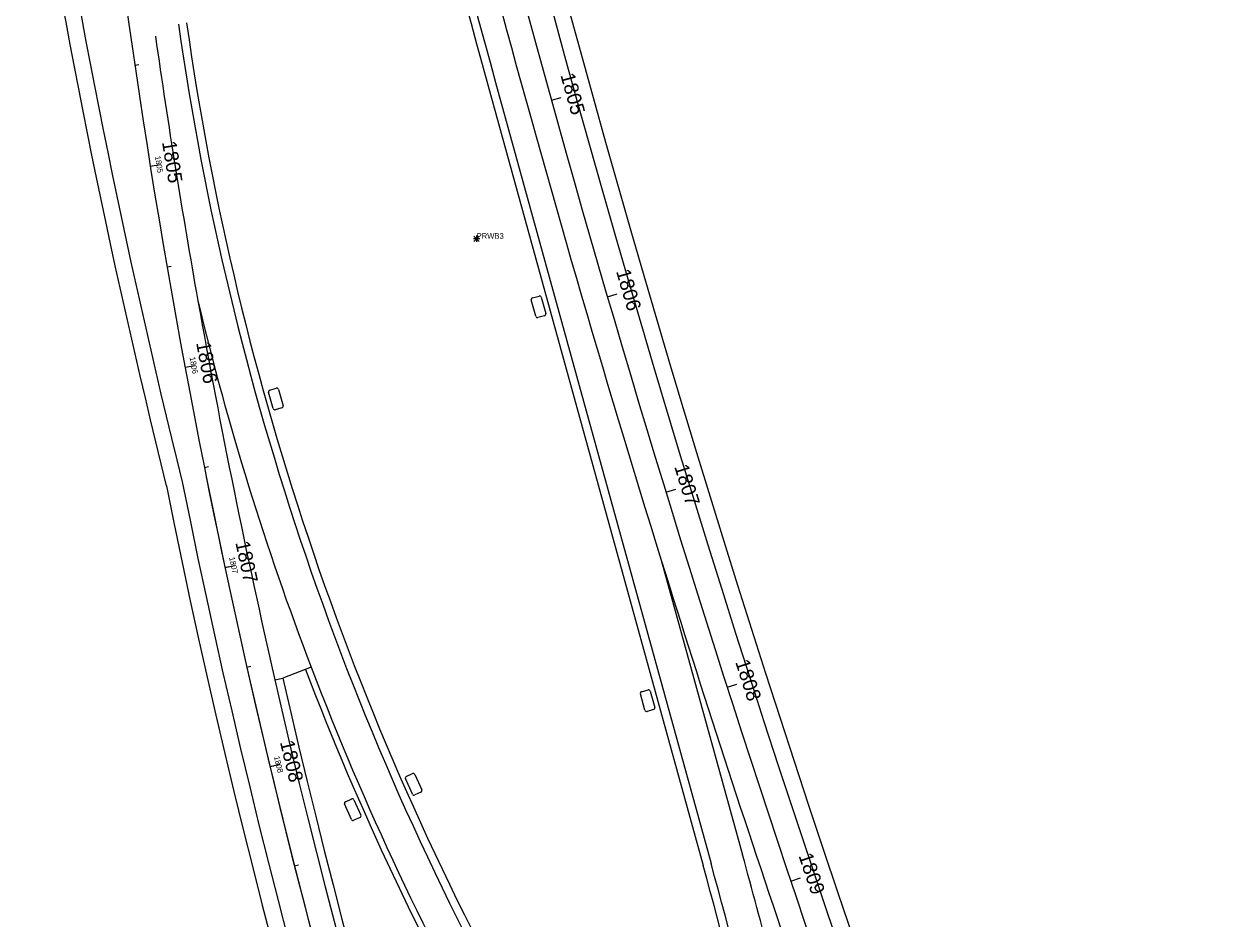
# Model space of a CAD drawing. Extents: x 8527 to 36635, y 12099 to 39012.
# Drawn here: x 20610 to 21201, y 35288 to 35726 of the extents above; entities that cross this region are included whole.
import ezdxf

# ---------------------------------------------------------------- set-up
doc = ezdxf.new("R2010")
doc.units = 0
for name, color, linetype in [('DR_P_Inlet_Protection', 7, 'Continuous'), ('GE_X_CL_20', 7, 'Continuous'), ('GK_Visualization', 7, 'Continuous'), ('MT_P_Text', 7, 'Continuous'), ('MT_P_Traffic_Attenuator', 7, 'Continuous'), ('PV_X_EOP', 7, 'Continuous'), ('PV_X_Shoulder', 7, 'Continuous'), ('SH_Cut_Line', 7, 'Continuous'), ('SH_Text', 7, 'Continuous')]:
    doc.layers.add(name, color=color, linetype=linetype)

msp = doc.modelspace()

# ---------------------------------------------------------------- linework, layer by layer
at = {"layer": 'DR_P_Inlet_Protection'}
for centre, radius, start, end in [((28229.01, 37734.18), 7639.44, 189.175, 202.716667), ((28229.01, 37734.18), 7651.44, 192.942703, 197.265545), ((24529.94, 36271.9), 3906.53, 186.21667, 209.21667), ((24529.94, 36271.9), 3894.53, 188.14872, 190.08077), ((24529.94, 36271.9), 3906.53, 191.33607, 209.21667)]:
    msp.add_arc(centre, radius, start, end, dxfattribs=at)
at = {"layer": 'GE_X_CL_20'}
for p, q in [((20664.65, 35705.75), (20666.63, 35706.04)), ((20672.21, 35656.32), (20674.19, 35656.64)), ((20680.41, 35607), (20682.38, 35607.34)), ((20689.23, 35557.78), (20691.2, 35558.15)), ((20698.69, 35508.69), (20700.65, 35509.08)), ((20708.77, 35459.71), (20710.73, 35460.13)), ((20719.48, 35410.87), (20721.43, 35411.31)), ((20730.81, 35362.17), (20732.75, 35362.64)), ((20742.76, 35313.63), (20744.7, 35314.12))]:
    msp.add_line(p, q, dxfattribs=at)
at = {"layer": 'GK_Visualization'}
for p, q in [((20833.49, 35620.67), (20830.37, 35620.67)), ((20830.6, 35619.33), (20833.26, 35622)), ((20830.6, 35622), (20833.26, 35619.33)), ((20831.93, 35622.23), (20831.93, 35619.11))]:
    msp.add_line(p, q, dxfattribs=at)
msp.add_arc((28229.01, 37734.18), 7639.44, 189.175, 202.716667, dxfattribs=at)
msp.add_arc((28229.01, 37734.18), 7639.44, 189.175, 202.716667, dxfattribs=at)
at = {"layer": 'MT_P_Text'}
for p, q in [((20672.21, 35656.32), (20677.15, 35657.11)), ((20689.23, 35557.78), (20694.15, 35558.7)), ((20708.77, 35459.71), (20713.66, 35460.75)), ((20730.81, 35362.17), (20735.67, 35363.34))]:
    msp.add_line(p, q, dxfattribs=at)
for centre, radius, start, end in [((28229.01, 37734.18), 7639.44, 189.175, 202.716667), ((24529.94, 36271.9), 3906.53, 186.21667, 209.21667)]:
    msp.add_arc(centre, radius, start, end, dxfattribs=at)
at = {"layer": 'MT_P_Traffic_Attenuator'}
msp.add_line((20837.38, 35696.15), (20942.83, 35313.7), dxfattribs=at)
for centre, radius, start, end in [((28229.01, 37734.18), 7619.44, 191.815419, 202.716667), ((28229.01, 37734.18), 7667.44, 192.942192, 195.414703), ((24466.65, 36439.98), 3901.57, 188.74698, 193.94525), ((22104.16, 35927.29), 1428.39, 188.08556, 209.54167), ((24529.94, 36271.9), 3926.53, 191.34141, 209.21667), ((24529.94, 36271.9), 3890.53, 192.86631, 209.21667), ((22104.16, 35927.29), 1451.39, 200.88855, 209.54167), ((17264.37, 34299.46), 3815.72, 9.126, 15.41472)]:
    msp.add_arc(centre, radius, start, end, dxfattribs=at)
at = {"layer": 'PV_X_EOP'}
msp.add_line((20922.35, 35463.23), (20962.11, 35319.01), dxfattribs=at)
for centre, radius, start, end in [((24529.94, 36271.9), 3894.53, 190.08077, 192.86631), ((22104.16, 35927.29), 1448.39, 193.45735, 200.88855), ((17264.37, 34299.46), 3835.72, 14.61747, 15.41472)]:
    msp.add_arc(centre, radius, start, end, dxfattribs=at)
at = {"layer": 'PV_X_Shoulder'}
for points in [[(20860.94, 35582.7), (20858.71, 35590.73)], [(20859.3, 35591.75), (20862.51, 35592.64)], [(20863.53, 35592.06), (20865.76, 35584.03)], [(20865.18, 35583.01), (20861.97, 35582.12)], [(20730.67, 35546.59), (20733.87, 35547.51)], [(20734.9, 35546.94), (20737.2, 35538.93)], [(20732.39, 35537.55), (20730.1, 35545.56)], [(20736.63, 35537.89), (20733.42, 35536.98)], [(20912.68, 35398.87), (20915.89, 35399.77)], [(20916.92, 35399.18), (20919.14, 35391.15)], [(20914.32, 35389.82), (20912.1, 35397.85)], [(20918.56, 35390.13), (20915.35, 35389.24)], [(20797.49, 35357.39), (20800.52, 35358.77)], [(20801.63, 35358.36), (20805.08, 35350.77)], [(20800.53, 35348.7), (20797.08, 35356.28)], [(20767.77, 35345.01), (20770.81, 35346.37)], [(20771.91, 35345.95), (20775.3, 35338.33)], [(20804.67, 35349.67), (20801.64, 35348.29)], [(20770.73, 35336.3), (20767.35, 35343.91)], [(20774.88, 35337.23), (20771.84, 35335.88)]]:
    msp.add_lwpolyline(points, dxfattribs=at)
for centre, start, end in [((20859.52, 35590.95), 105.5, 195.5), ((20862.73, 35591.84), 15.5, 105.5), ((20861.74, 35582.92), 195.5, 285.5), ((20864.96, 35583.81), 285.5, 15.5), ((20730.9, 35545.79), 106, 196), ((20734.1, 35546.71), 16, 106), ((20733.19, 35537.78), 196, 286), ((20736.4, 35538.7), 286, 16), ((20912.9, 35398.07), 105.5, 195.5), ((20916.11, 35398.96), 15.5, 105.5), ((20915.13, 35390.04), 195.5, 285.5), ((20918.34, 35390.93), 285.5, 15.5), ((20797.84, 35356.63), 114.5, 204.5), ((20800.87, 35358.01), 24.5, 114.5), ((20771.15, 35345.61), 24, 114), ((20801.29, 35349.04), 204.5, 294.5), ((20804.33, 35350.43), 294.5, 24.5), ((20768.11, 35344.25), 114, 204), ((20771.5, 35336.64), 204, 294), ((20774.54, 35338), 294, 24)]:
    msp.add_arc(centre, 0.833, start, end, dxfattribs=at)
at = {"layer": 'SH_Cut_Line'}
for p, q in [((20868.56, 35688.49), (20873.38, 35689.83)), ((20895.97, 35592.32), (20900.77, 35593.72)), ((20924.63, 35496.52), (20929.41, 35497.98)), ((20954.55, 35401.1), (20959.31, 35402.62)), ((20985.71, 35306.08), (20990.45, 35307.67))]:
    msp.add_line(p, q, dxfattribs=at)
at = {"layer": 'SH_Text'}
for p, q in [((20841.24, 35697.21), (20946.69, 35314.76)), ((20750.96, 35410.86), (20737.09, 35405.57)), ((20733.19, 35404.68), (20737.09, 35405.57))]:
    msp.add_line(p, q, dxfattribs=at)
for centre, radius, start, end in [((28229.01, 37734.18), 7627.44, 191.807877, 202.716667), ((28229.01, 37734.18), 7663.44, 192.942703, 195.414703), ((24466.64, 36440.07), 3893.57, 188.74831, 193.94658), ((22104.16, 35927.29), 1432.39, 188.08556, 209.54167), ((24529.94, 36271.9), 3918.53, 191.33607, 209.21667), ((28229.01, 37734.18), 7651.44, 197.265545, 198.78578), ((22104.16, 35927.29), 1448.39, 200.88855, 209.54167), ((24531.79, 36272.61), 3896.49, 192.87045, 209.21252), ((17264.37, 34299.46), 3819.72, 9.126, 15.41472)]:
    msp.add_arc(centre, radius, start, end, dxfattribs=at)

# ---------------------------------------------------------------- texts
at = {"layer": 'GE_X_CL_20'}
for s, rotation, p in [('1805', 279.06623, (20674.5, 35661.03)), ('1806', 280.53289, (20691.4, 35562.56)), ('1807', 281.99956, (20710.8, 35464.59)), ('1808', 283.46623, (20732.74, 35366.99))]:
    msp.add_text(s, height=2.8, rotation=rotation, dxfattribs=at).set_placement(p)
at = {"layer": 'GK_Visualization'}
msp.add_text('PRWB3', height=2.8, dxfattribs=at).set_placement((20831.93, 35620.67))
at = {"layer": 'MT_P_Text'}
for s, rotation, p in [('1805', 279.06623, (20677.93, 35668.09)), ('1806', 280.53289, (20694.64, 35569.72)), ('1807', 281.99956, (20713.84, 35471.92)), ('1808', 283.46623, (20735.64, 35374.21))]:
    msp.add_text(s, height=7, rotation=rotation, dxfattribs=at).set_placement(p)
at = {"layer": 'SH_Cut_Line'}
for s, rotation, p in [('1805', 285.53221, (20872.92, 35700.83)), ('1806', 286.28221, (20900.15, 35604.74)), ('1807', 287.03221, (20928.62, 35509.12)), ('1808', 287.78221, (20958.46, 35413.46)), ('1809', 288.53221, (20989.42, 35318.6))]:
    msp.add_text(s, height=7, rotation=rotation, dxfattribs=at).set_placement(p)

doc.saveas('drawing.dxf')
